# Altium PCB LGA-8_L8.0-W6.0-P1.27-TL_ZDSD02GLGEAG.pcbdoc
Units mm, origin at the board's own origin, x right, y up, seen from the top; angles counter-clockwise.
Board outline 21.75 x 18.85 mm, 2 copper layers (Top Layer, Bottom Layer), stack 0 mm thick; 1 components, 0 nets, 8 pads, 0 vias.
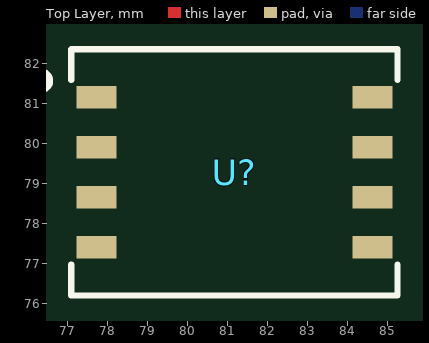
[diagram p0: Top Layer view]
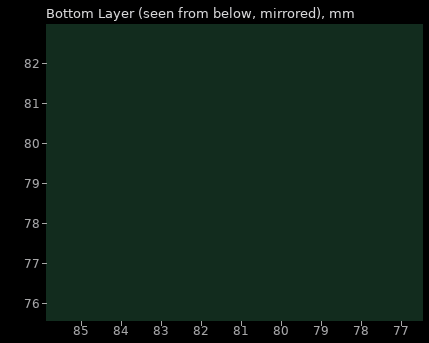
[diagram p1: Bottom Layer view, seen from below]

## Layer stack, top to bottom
Top Layer: signal copper (thickness not stored)
Bottom Layer: signal copper (thickness not stored)

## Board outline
91.602,69.85 69.85,69.85 69.85,88.702 91.602,88.702

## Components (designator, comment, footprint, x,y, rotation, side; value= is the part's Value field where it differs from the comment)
U? "" LGA-8_L8.0-W6.0-P1.27-TL_ZDSD02GLGEAG 81.176,79.276 r0 top

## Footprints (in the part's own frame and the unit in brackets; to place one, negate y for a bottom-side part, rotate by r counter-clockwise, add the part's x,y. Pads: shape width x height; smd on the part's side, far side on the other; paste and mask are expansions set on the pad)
LGA-8_L8.0-W6.0-P1.27-TL_ZDSD02GLGEAG [mm]
  rect 1x0.56 smd: 1(-3.45,1.875) 2(-3.45,0.625) 3(-3.45,-0.625) 4(-3.45,-1.875) 5(3.45,-1.875) 6(3.45,-0.625) 7(3.45,0.625) 8(3.45,1.875)
  silkscreen extent -4.98,-3.08 4.08,3.08

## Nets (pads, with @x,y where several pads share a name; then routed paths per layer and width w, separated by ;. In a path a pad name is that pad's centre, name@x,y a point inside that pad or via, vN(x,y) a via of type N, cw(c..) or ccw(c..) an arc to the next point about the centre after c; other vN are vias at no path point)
pads on no net: U?.1 U?.2 U?.3 U?.4 U?.5 U?.6 U?.7 U?.8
